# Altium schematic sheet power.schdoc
size 277 x 190 mm; Device: default297x210; Symbol: default297x210; Name: default297x210; Size: "A4"; Id: /; File: power; Sheet: /
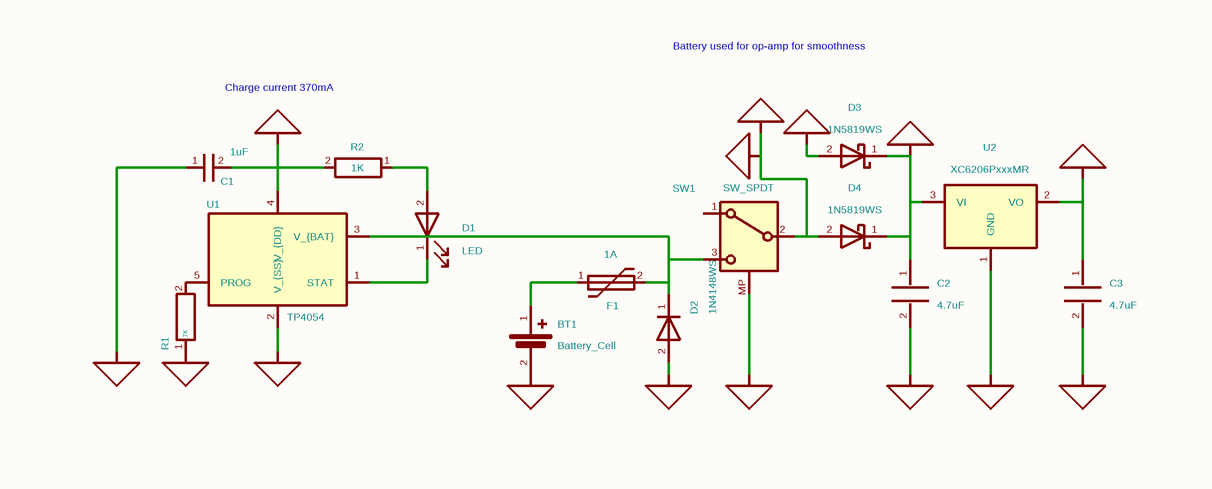
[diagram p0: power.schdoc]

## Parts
BT1  value Battery_Cell  [Connector_JST:JST_PH_S2B-PH-K_1x02_P2.00mm_Horizontal]  (hidden comment: Device_Battery_Cell)
C1  value 1uF  [Capacitor_SMD:C_0603_1608Metric]  (hidden comment: Device_C_Small)
C2  value 4.7uF  [Capacitor_SMD:C_0805_2012Metric]  (hidden comment: Device_C)
C3  value 4.7uF  [Capacitor_SMD:C_0805_2012Metric]  (hidden comment: Device_C)
D1  value LED  [LED_SMD:LED_0805_2012Metric]  (hidden comment: Device_LED)
D2  value 1N4148WS  [Diode_SMD:D_SOD-323]  (hidden comment: Diode_SM4001)
D3  value 1N5819WS  [Diode_SMD:D_SOD-323]  (hidden comment: Diode_1N5819WS)
D4  value 1N5819WS  [Diode_SMD:D_SOD-323]  (hidden comment: Diode_1N5819WS)
F1  value 1A  [Fuse:Fuse_0805_2012Metric]  (hidden comment: Device_Polyfuse)
R1  value 2.7K  [Resistor_SMD:R_0603_1608Metric]  (hidden comment: Device_R)
R2  value 1K  [Resistor_SMD:R_0603_1608Metric]  (hidden comment: Device_R)
SW1  value SW_SPDT  [Button_Switch_THT:SW_Slide_SPDT_Angled_CK_OS102011MA1Q]  (hidden comment: Switch_SW_SPDT)
U1  value TP4054  [Package_TO_SOT_SMD:SOT-23-5]  (hidden comment: Battery_Management_MCP73831-2-OT)
U2  value XC6206PxxxMR  [Package_TO_SOT_SMD:SOT-23-3]  (hidden comment: Regulator_Linear_XC6206PxxxMR)

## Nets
power_+3.3V: C3.1 U2.2(VO)
power_+5V: C1.2 D3.2(A) R2.2 U1.4(V_{DD})
power_+BATT: C2.1 D3.1(K) D4.1(K) D4.2(A) SW1.2(B) U2.3(VI)  [also labelled power_PWR_FLAG]
power_GND: BT1.2(-) C1.1 C2.2 C3.2 D2.2(A) R1.1 SW1.MP U1.2(V_{SS}) U2.1(GND)
NetBT1_1: BT1.1(+) F1.1
NetD1_1: D1.1(K) U1.1(STAT)
NetD1_2: D1.2(A) R2.1
NetD2_1: D2.1(K) F1.2 SW1.3(C) U1.3(V_{BAT})
NetR1_2: R1.2 U1.5(PROG)

Not connected (* = marked no-connect by the designer): SW1 1(A)

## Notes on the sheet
- Charge current 370mA
- Battery used for op-amp for smoothness

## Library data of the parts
BT1 = Device_Battery_Cell: Single-cell battery; Sim.Device: V; Sim.Type: DC; Sim.Pins: 1=+ 2=-; UniqueId: c9182c8b26c7f8f5; Attribute1: BT1; AddInBom: yes
C1 = Device_C_Small: Unpolarized capacitor, small symbol; ki_fp_filters: C_*; UniqueId: b4693cfd16d534cd; Attribute1: C1; KiLib_Generator: SMD_2terminal_chip_molded; AddInBom: yes
C2 = Device_C: Unpolarized capacitor; ki_fp_filters: C_*; UniqueId: a2c5d49bc5dde298; Attribute1: C2; KiLib_Generator: SMD_2terminal_chip_molded; AddInBom: yes
C3 = Device_C: Unpolarized capacitor; ki_fp_filters: C_*; UniqueId: cc82bf2c2e22e605; Attribute1: C2; KiLib_Generator: SMD_2terminal_chip_molded; AddInBom: yes
D1 = Device_LED: Light emitting diode; Sim.Pins: 1=K 2=A; ki_fp_filters: LED* LED_SMD:* LED_THT:*; UniqueId: 6eb2f7ba7a12821c; Attribute1: D1; KiLib_Generator: SMD_2terminal_chip_molded; AddInBom: yes
D2 = Diode_SM4001: 50V 1A General Purpose Rectifier Diode, MELF; Sim.Device: D; Sim.Pins: 1=K 2=A; UniqueId: cca08e5caf06c018; AddInBom: yes
D3 = Diode_1N5819WS: 40V 600mV@1A 1A SOD-323 Schottky Barrier Diodes, SOD-323; UniqueId: 81689f1d3303caec; AddInBom: yes
D4 = Diode_1N5819WS: 40V 600mV@1A 1A SOD-323 Schottky Barrier Diodes, SOD-323; UniqueId: 6a4368da87585c93; AddInBom: yes
F1 = Device_Polyfuse: Resettable fuse, polymeric positive temperature coefficient; ki_fp_filters: *polyfuse* *PTC*; UniqueId: 09f31a4987c8a883; Attribute1: F1; AddInBom: yes
R1 = Device_R: Resistor; UniqueId: 353b166cc2dee846; AddInBom: yes
R2 = Device_R: Resistor; ki_fp_filters: R_*; UniqueId: 6f63fc6711cfa315; Attribute1: R2; KiLib_Generator: SMD_2terminal_chip_molded; AddInBom: yes
SW1 = Switch_SW_SPDT: Switch, single pole double throw; UniqueId: c39dab7994ba8bcb; Attribute1: SW1; AddInBom: yes
U1 = Battery_Management_MCP73831-2-OT: Single cell, Li-Ion/Li-Po charge management controller, 4.20V, Tri-State Status Output, in SOT23-5 package; ki_fp_filters: SOT?23*; UniqueId: 1bdc0ab44f99f92d; Attribute1: U1; AddInBom: yes
U2 = Regulator_Linear_XC6206PxxxMR: Positive 60-250mA Low Dropout Regulator, Fixed Output, SOT-23; ki_fp_filters: SOT?23?3*; UniqueId: 48f0ae2437312dae; Attribute1: U2; AddInBom: yes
